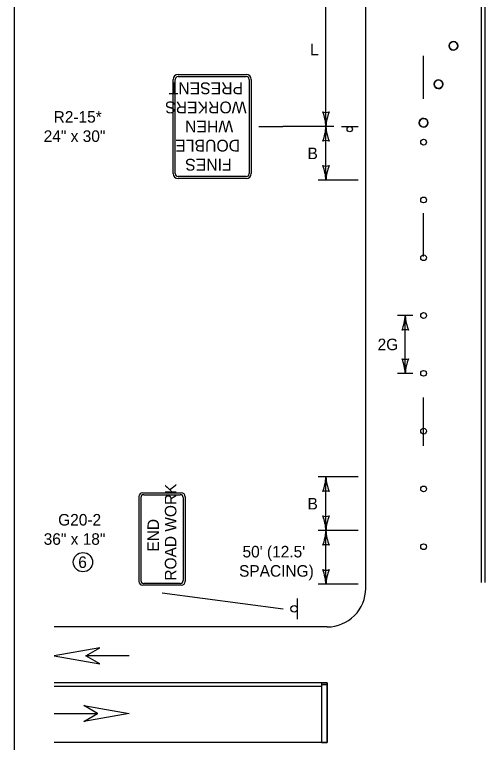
# Model space of a CAD drawing. Extents: x 49991.4 to 50021, y 49987.6 to 50011.4.
# Drawn here: x 49999.384 to 50001.827, y 49992.224 to 49996.003 of the extents above; entities that cross this region are included whole.
import ezdxf

# ---------------------------------------------------------------- set-up
doc = ezdxf.new("R2010")
doc.units = 0
for name, color, linetype in [('Level 1', 7, 'Continuous'), ('Level 2', 7, 'Continuous'), ('Level 3', 7, 'Continuous')]:
    doc.layers.add(name, color=color, linetype=linetype)

msp = doc.modelspace()

# ---------------------------------------------------------------- linework, layer by layer
at = {"layer": 'Level 1'}
for p, q in [((50001.2058, 49993.024), (50001.2058, 49998.8719)), ((50001.8058, 49995.4153), (50001.8058, 49996.2021)), ((50001.8258, 49995.4153), (50001.8258, 49996.2021)), ((50001.5059, 49995.5651), (50001.5059, 49995.7891)), ((50000.2317, 49995.6917), (50000.5861, 49995.6917)), ((50000.2064, 49995.177), (50000.2064, 49995.6664)), ((50000.2169, 49995.177), (50000.2169, 49995.6664)), ((50000.2317, 49995.6812), (50000.5861, 49995.6812)), ((50000.6009, 49995.6664), (50000.6009, 49995.177)), ((50000.6114, 49995.6664), (50000.6114, 49995.177)), ((50001.8058, 49995.3665), (50001.8058, 49995.6141)), ((50001.8258, 49995.3141), (50001.8258, 49995.6141)), ((50001.0794, 49995.4217), (50001.1658, 49995.4217)), ((50001.8058, 49995.0665), (50001.8058, 49995.3665)), ((50001.8258, 49995.0141), (50001.8258, 49995.3141)), ((50000.5861, 49995.1622), (50000.2317, 49995.1622)), ((50000.5861, 49995.1517), (50000.2317, 49995.1517)), ((50000.4089, 49995.1517), (50000.4089, 49995.1517)), ((50001.8058, 49994.7665), (50001.8058, 49995.0665)), ((50001.8258, 49994.7141), (50001.8258, 49995.0141)), ((50001.5059, 49994.7461), (50001.5059, 49994.9711)), ((50001.8058, 49994.4141), (50001.8058, 49994.7665)), ((50001.8258, 49994.4141), (50001.8258, 49994.7141)), ((50001.8058, 49994.1141), (50001.8058, 49994.4141)), ((50001.8258, 49994.1141), (50001.8258, 49994.4141)), ((50001.8058, 49993.8665), (50001.8058, 49994.1141)), ((50001.8258, 49993.8141), (50001.8258, 49994.1141)), ((50001.5059, 49993.764), (50001.5059, 49994.014)), ((50001.8058, 49993.5782), (50001.8058, 49993.8665)), ((50001.8258, 49993.5024), (50001.8258, 49993.8141)), ((50001.8058, 49993.2782), (50001.8058, 49993.5782)), ((50000.0286, 49993.5), (50000.0286, 49993.06)), ((50000.0486, 49993.52), (50000.2486, 49993.52)), ((50000.0536, 49993.51), (50000.2436, 49993.51)), ((50000.2687, 49993.4999), (50000.2687, 49993.0599)), ((50001.8257, 49993.5153), (50001.8257, 49993.5174)), ((50001.8258, 49993.2782), (50001.8258, 49993.5024)), ((50000.0386, 49993.495), (50000.0386, 49993.065)), ((50000.2586, 49993.495), (50000.2586, 49993.065)), ((50001.8058, 49993.054), (50001.8058, 49993.2782)), ((50001.8258, 49993.054), (50001.8258, 49993.2782)), ((50001.8257, 49993.2153), (50001.8257, 49993.2174)), ((50000.2436, 49993.05), (50000.0536, 49993.05)), ((50000.2486, 49993.04), (50000.0486, 49993.04)), ((50000.8507, 49992.9706), (50000.8507, 49992.864)), ((50001.0058, 49992.824), (49999.5889, 49992.824)), ((49999.979, 49992.6741), (49999.7531, 49992.6741)), ((49999.979, 49992.6737), (49999.7531, 49992.6737)), ((50001.0058, 49992.5341), (49999.5889, 49992.5341)), ((50000.9758, 49992.5341), (50000.9758, 49992.224)), ((50000.9758, 49992.5241), (50001.0058, 49992.5241)), ((50001.0058, 49992.5341), (50001.0058, 49992.224)), ((50000.9758, 49992.5141), (49999.5889, 49992.5141)), ((49999.5889, 49992.3741), (49999.8148, 49992.3741)), ((49999.5889, 49992.3737), (49999.8148, 49992.3737)), ((50001.0058, 49992.224), (49999.5889, 49992.224))]:
    msp.add_line(p, q, dxfattribs=at)
for points in [[(49999.3835, 49998.9992), (50016.7501, 49998.9992), (50016.7501, 49987.7988), (49999.3835, 49987.7988)], [(49999.8254, 49992.7157), (49999.5889, 49992.6741), (49999.8254, 49992.6321), (49999.7532, 49992.6741)], [(49999.7425, 49992.4157), (49999.979, 49992.3741), (49999.7425, 49992.3321), (49999.8147, 49992.3741)]]:
    msp.add_lwpolyline(points, close=True, dxfattribs=at)
for points in [[(50001.0058, 49992.5341), (50000.9758, 49992.5341), (50000.9758, 49992.5241), (50001.0058, 49992.5241), (50001.0058, 49992.5341)], [(50000.9758, 49992.224), (50001.0058, 49992.224), (50001.0058, 49992.5241), (50000.9758, 49992.5241), (50000.9758, 49992.224)]]:
    msp.add_lwpolyline(points, dxfattribs=at)
for centre, radius in [((50001.6608, 49995.8408), 0.0225), ((50001.5834, 49995.6411), 0.0225), ((50001.5059, 49995.4415), 0.0225), ((50001.1226, 49995.4081), 0.0137), ((50001.5059, 49995.3403), 0.015), ((50001.5059, 49995.0403), 0.015), ((50001.5059, 49994.7403), 0.015), ((50001.5059, 49994.4403), 0.015), ((50001.5059, 49994.1403), 0.015), ((50001.5059, 49993.8403), 0.015), ((50001.5059, 49993.5403), 0.015), ((50001.5059, 49993.2403), 0.015), ((50000.8339, 49992.9173), 0.0169)]:
    msp.add_circle(centre, radius, dxfattribs=at)
for centre, radius, start, end in [((50001.6608, 49995.8408), 0.0225, 176.6361, 356.6361), ((50001.6608, 49995.8408), 0.0225, 356.6361, 176.6361), ((50000.2317, 49995.6664), 0.0253, 90, 180), ((50000.5861, 49995.6664), 0.0253, 360, 90), ((50000.2317, 49995.6664), 0.0148, 90, 180), ((50000.5861, 49995.6664), 0.0148, 360, 90), ((50001.5834, 49995.6411), 0.0225, 356.6361, 176.6361), ((50001.5834, 49995.6411), 0.0225, 176.6361, 356.6361), ((50001.5059, 49995.4415), 0.0225, 356.6361, 176.6361), ((50001.5059, 49995.4415), 0.0225, 176.6361, 356.6361), ((50000.2317, 49995.177), 0.0253, 180, 270), ((50000.2317, 49995.177), 0.0148, 180, 270), ((50000.5861, 49995.177), 0.0148, 270, 360), ((50000.5861, 49995.177), 0.0253, 270, 360), ((50000.0486, 49993.5), 0.02, 90, 180), ((50000.0536, 49993.495), 0.015, 90, 180), ((50000.2436, 49993.495), 0.015, 360, 90), ((50000.2486, 49993.4999), 0.02, 360, 90), ((50000.0486, 49993.06), 0.02, 180, 270), ((50000.0536, 49993.065), 0.015, 180, 270), ((50000.2436, 49993.065), 0.015, 270, 360), ((50000.2486, 49993.0599), 0.02, 270, 360), ((50001.0058, 49993.024), 0.2, 270, 0.0007)]:
    msp.add_arc(centre, radius, start, end, dxfattribs=at)
at = {"layer": 'Level 2'}
msp.add_circle((49999.7385, 49993.1599), 0.0501, dxfattribs=at)
at = {"layer": 'Level 3'}
for p, q in [((50000.9994, 49995.4217), (50000.9994, 49996.2217)), ((50000.6514, 49995.4217), (50000.7755, 49995.4217)), ((50001.0394, 49995.4217), (50000.7755, 49995.4217)), ((50001.0394, 49995.4217), (50000.9594, 49995.4217)), ((50000.9994, 49995.1428), (50000.9994, 49995.4217)), ((50001.1658, 49995.1428), (50000.9594, 49995.1428)), ((50001.4509, 49994.4403), (50001.3709, 49994.4403)), ((50001.4109, 49994.1403), (50001.4109, 49994.4403)), ((50001.4509, 49994.1403), (50001.3709, 49994.1403)), ((50001.1658, 49993.6029), (50000.9594, 49993.6029)), ((50000.9994, 49993.3239), (50000.9994, 49993.6029)), ((50001.1658, 49993.3239), (50000.9594, 49993.3239)), ((50000.9994, 49993.045), (50000.9994, 49993.3239)), ((50001.1658, 49993.045), (50000.9594, 49993.045)), ((50000.1486, 49993), (50000.7769, 49992.9173))]:
    msp.add_line(p, q, dxfattribs=at)
for centre, radius, start, end in [((50000.9994, 49995.5499), 0.0548, 252.1388, 287.8612), ((50000.7667, 49995.4102), 0.233, 2.8273, 22.0772), ((50001.2215, 49995.4125), 0.2223, 157.456, 177.6395), ((50000.7772, 49995.4309), 0.2223, 337.456, 357.6395), ((50001.2321, 49995.4332), 0.233, 182.8273, 202.0772), ((50000.9994, 49995.2935), 0.0548, 72.1388, 107.8612), ((50000.9994, 49995.271), 0.0548, 252.1388, 287.8612), ((50000.7667, 49995.1313), 0.233, 2.8273, 22.0772), ((50001.2215, 49995.1336), 0.2223, 157.456, 177.6395), ((50001.1888, 49994.4495), 0.2223, 337.456, 357.6395), ((50001.6436, 49994.4518), 0.233, 182.8273, 202.0772), ((50001.4109, 49994.3121), 0.0548, 72.1388, 107.8612), ((50001.4109, 49994.2685), 0.0548, 252.1388, 287.8612), ((50001.1782, 49994.1288), 0.233, 2.8273, 22.0772), ((50001.633, 49994.1311), 0.2223, 157.456, 177.6395), ((50000.7772, 49993.612), 0.2223, 337.456, 357.6395), ((50001.2321, 49993.6144), 0.233, 182.8273, 202.0772), ((50000.9994, 49993.4746), 0.0548, 72.1388, 107.8612), ((50000.9994, 49993.4522), 0.0548, 252.1388, 287.8612), ((50000.7667, 49993.3125), 0.233, 2.8273, 22.0772), ((50001.2215, 49993.3148), 0.2223, 157.456, 177.6395), ((50000.7772, 49993.3331), 0.2223, 337.456, 357.6395), ((50001.2321, 49993.3354), 0.233, 182.8273, 202.0772), ((50000.9994, 49993.1957), 0.0548, 72.1388, 107.8612), ((50000.9994, 49993.1733), 0.0548, 252.1388, 287.8612), ((50000.7667, 49993.0335), 0.233, 2.8273, 22.0772), ((50001.2215, 49993.0359), 0.2223, 157.456, 177.6395)]:
    msp.add_arc(centre, radius, start, end, dxfattribs=at)

# ---------------------------------------------------------------- texts
at = {"layer": 'Level 1'}
for s, height, rotation, p in [('PRESENT', 0.06118, 180, (50000.5694, 49995.6506)), ('WORKERS', 0.06118, 180, (50000.5875, 49995.5514)), ('WHEN', 0.06118, 180, (50000.5181, 49995.4523)), ('DOUBLE', 0.06118, 180, (50000.5536, 49995.3531)), ('FINES', 0.06118, 180, (50000.5101, 49995.254)), ('ROAD WORK', 0.06, 90, (50000.2233, 49993.0641)), ('END', 0.06, 90, (50000.1333, 49993.2148))]:
    msp.add_text(s, height=height, rotation=rotation, dxfattribs=at).set_placement(p)
at = {"layer": 'Level 2'}
for s, p in [('L', (50000.917, 49995.7917)), ('R2-15*', (49999.5862, 49995.4417)), ('24" x 30"', (49999.5346, 49995.3417)), ('B', (50000.9039, 49995.2522)), ('2G', (50001.2673, 49994.2603)), ('B', (50000.9039, 49993.4334)), ('G20-2', (49999.6098, 49993.35)), ('36" x 18"', (49999.5346, 49993.25)), ("50' (12.5'", (50000.5663, 49993.1845)), ('6', (49999.714, 49993.1299)), ('SPACING) ', (50000.5484, 49993.0845))]:
    msp.add_text(s, height=0.06, dxfattribs=at).set_placement(p)

doc.saveas('drawing.dxf')
